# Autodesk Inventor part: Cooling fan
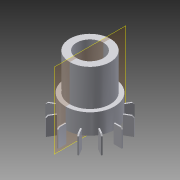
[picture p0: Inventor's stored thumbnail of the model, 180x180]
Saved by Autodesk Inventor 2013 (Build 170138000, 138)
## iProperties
Created: 2008-06
Part Number: Cooling fan
Document SubType Name: Modeling
Designer: tangg
Density: 1.4 g/cm^3
Mass: 5.22571 g
Surface Area: 24.131 cm^2
Volume: 5.22571 cm^3
Stock Number: Cooling fan
Material: PVC-U
Author: tangg
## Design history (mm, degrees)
sketch "Sketch1"
  geometry: L1 (0, 0)-(7.938, 0); L2 (7.938, 0)-(7.938, -14.287); L3 (7.938, -14.287)-(0, -14.287); L4 (0, -14.287)-(0, 0); L5 (0, -14.287)-(9.525, -14.287); L6 (9.525, -14.287)-(9.525, -22.225); L7 (9.525, -22.225)-(0, -22.225); L8 (0, -22.225)-(0, -14.287)
  constraints: 16 end point
revolve "Revolution1" sketch "Sketch1" stored, may be unused: angle "d0" = 90 deg
sketch "Sketch2"
  geometry: L1 (-14.287, 7.938)-(-14.287, -7.938) reference; L2 (0, 7.938)-(0, -7.938) reference; L3 (-14.287, -9.525)-(-22.225, -9.525) reference; L4 (-19.831, -9.525)-(-26.889, -9.525); L5 (-26.889, -9.525)-(-26.889, -12.7); L6 (-26.889, -12.7)-(-20.466, -12.7); L7 (-19.831, -12.065)-(-19.831, -9.525); L8 (-20.466, -12.7)-(-19.831, -12.065); 2 further points
  constraints: 10 end point, 3 point on line
  dimensions: "d1" = 0.635 distance of L6.end point (-19.831, -12.7); "d2" = 0.635 distance of L7.start point (-19.831, -12.7) (= d1)
extrude "Extrusion1" join sketch "Sketch2" stored distance "d3" = 0.508; taper "d4" = 0 deg
pattern_circular "Circular Pattern1" dims angle "d6" = 360 deg
sketch "Sketch3"
  geometry: C1 r 5.25 at (0, 0); 1 further point
  constraints: 1 centre point, 1 coincident
  dimensions: "d10" = 10.5 diameter of C1
extrude "Extrusion2" cut sketch "Sketch3" stored distance "d8" = 10; taper "d9" = 0 deg
body "Solid1"
node "Projected Loop1"
